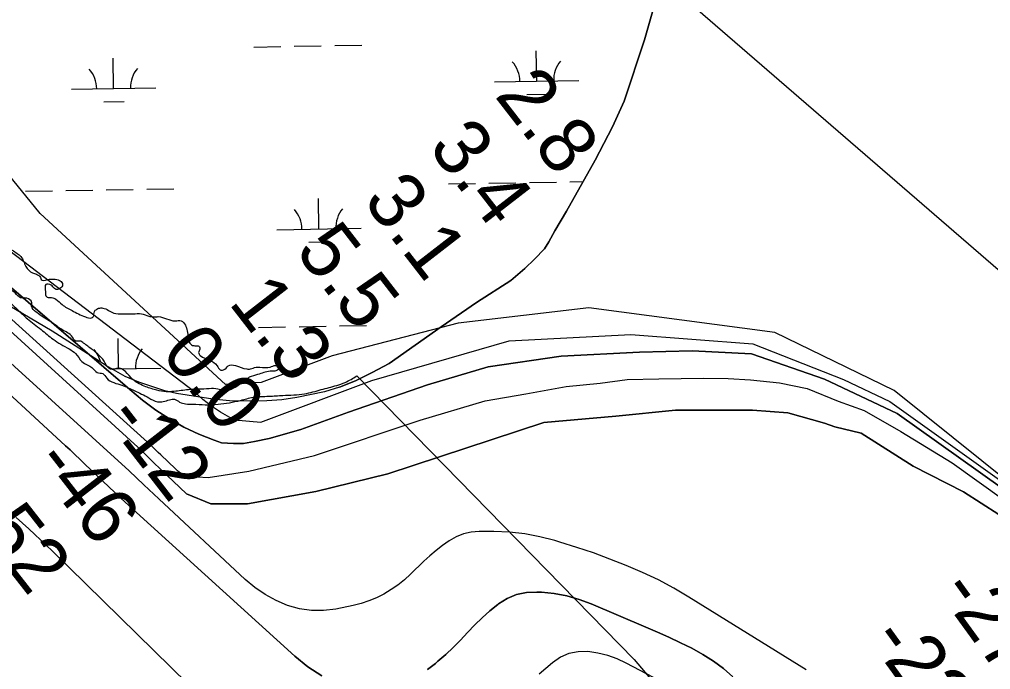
# Model space of a CAD drawing. Extents: x 3892998 to 3931244, y 278583 to 304547.
# Drawn here: x 3911880 to 3913032, y 292369 to 293140 of the extents above; entities that cross this region are included whole.
import ezdxf

# ---------------------------------------------------------------- set-up
doc = ezdxf.new("R2010")
doc.units = 0
for name, color, linetype in [('V-GRID-MAJR', 7, 'Continuous'), ('V-RIVR-EDGE', 7, 'Continuous'), ('V-RIVR-RANG', 7, 'Continuous'), ('V-TOPO-DPTH', 7, 'Continuous'), ('V-TOPO-MAJR', 7, 'Continuous'), ('V-TOPO-MINR', 7, 'Continuous'), ('V-TOPO-SHOR', 7, 'Continuous'), ('V-TOPO-WATR', 7, 'Continuous'), ('V-UTIL-LINE', 7, 'Continuous'), ('V-WETL-SWMP', 7, 'Continuous')]:
    doc.layers.add(name, color=color, linetype=linetype)

msp = doc.modelspace()

# ---------------------------------------------------------------- linework, layer by layer
at = {"layer": 'V-GRID-MAJR'}
msp.add_spline([(3913205.7, 284291.2), (3913100.9, 290347.6), (3912996, 296407.6), (3912891.1, 302467.5), (3912891, 302471)], degree=3, dxfattribs=at)
at = {"layer": 'V-RIVR-EDGE'}
for p, q in [((3912279.7, 292717.3), (3912608.9, 292380.9)), ((3912608.9, 292380.9), (3912865, 292078.8))]:
    msp.add_line(p, q, dxfattribs=at)
msp.add_spline([(3911791.9, 293031.1), (3911788.2, 293020.2), (3911781.2, 293014.2), (3911750.3, 292994.6), (3911722.9, 292976.8), (3911718.6, 292974.1), (3911715.9, 292969.8), (3911715.6, 292965.1), (3911717.6, 292958.5), (3911723.9, 292953.5), (3911730.9, 292952.8), (3911742.5, 292955.1), (3911750.8, 292957.7), (3911758.1, 292958), (3911775.4, 292952), (3911792, 292943.3), (3911808, 292932), (3911822.9, 292920), (3911838.5, 292902), (3911846.8, 292890), (3911854.7, 292878), (3911865.3, 292870.3), (3911877, 292862.6), (3911881.3, 292859), (3911887.2, 292847.3), (3911895.2, 292839.7), (3911899.8, 292838), (3911904.5, 292834), (3911905.5, 292831.7), (3911912.8, 292831.6), (3911927.1, 292830.6), (3911929.1, 292829.3), (3911930.7, 292824.3), (3911928.7, 292822), (3911923.4, 292820), (3911919.4, 292823), (3911917.1, 292825), (3911911.1, 292826), (3911910.4, 292817.3), (3911910.4, 292815), (3911912.7, 292810.7), (3911917.7, 292810.3), (3911923, 292808.3), (3911930.3, 292802), (3911942, 292795), (3911957.9, 292787.3), (3911965.2, 292786.3), (3911967.2, 292787.6), (3911968.6, 292793.9), (3911969.6, 292795.2), (3911973.6, 292797.6), (3911978.6, 292797.9), (3911991.5, 292791.9), (3912002.5, 292791.2), (3912014.4, 292791.1), (3912024.4, 292791.1), (3912033.1, 292788.4), (3912038.4, 292787.4), (3912044.4, 292787.7), (3912064.3, 292782.7), (3912071.6, 292782.7), (3912074.3, 292780.7), (3912079.2, 292767), (3912080.5, 292759.1), (3912083.9, 292754.1), (3912089.2, 292753.1), (3912093.2, 292752), (3912093.5, 292749.1), (3912092.1, 292745.1), (3912094.1, 292741.7), (3912105.1, 292736.1), (3912114.1, 292729.4), (3912117.7, 292724.7), (3912121.7, 292724.4), (3912127.4, 292729.3), (3912136, 292729.7), (3912149.3, 292725.6), (3912153.6, 292725.6), (3912160.3, 292727.6), (3912164.9, 292727.6), (3912176.9, 292727.9), (3912183.9, 292729.9), (3912189.2, 292727.9), (3912187.5, 292725.2), (3912176.9, 292722.9), (3912162.2, 292719), (3912152.3, 292715.7), (3912141.6, 292707.7), (3912130.6, 292701.4), (3912121.6, 292699.8), (3912115, 292701.8), (3912104.7, 292702.1), (3912080.1, 292700.9), (3912062.8, 292698.9), (3912053.8, 292698.6), (3912042.8, 292700.3), (3912029.5, 292704.6), (3912014.3, 292713), (3911995.7, 292726.3), (3911991.7, 292725), (3911984, 292728), (3911981.4, 292732.4), (3911974.8, 292741.4), (3911965.8, 292748.7), (3911955.8, 292756.4), (3911951.2, 292758.7), (3911946.5, 292758.7), (3911942.6, 292763.4), (3911929.9, 292772.4), (3911919.6, 292779.7), (3911909, 292786.4), (3911899.4, 292793.1), (3911894.1, 292800.1), (3911894.4, 292804.1), (3911893.4, 292806.4), (3911886.5, 292809.8), (3911881.1, 292810.1), (3911874.5, 292815.8), (3911864.6, 292822.1), (3911848, 292836.8), (3911832, 292848.1), (3911815.8, 292856.1), (3911809.4, 292857.5), (3911808.8, 292854.8), (3911810.4, 292849.5), (3911813.1, 292846.5), (3911818.4, 292845.8), (3911826.7, 292845.8), (3911827.7, 292842.8), (3911832, 292831.5), (3911837.3, 292826.8), (3911850.9, 292816.8), (3911867.5, 292804.8), (3911877.5, 292796.1), (3911889.1, 292785.1), (3911905.3, 292772.5), (3911919.6, 292760.8), (3911938.5, 292749.4), (3911946.2, 292743.8), (3911953.8, 292734.4), (3911960.1, 292730.4), (3911965.7, 292727.4), (3911972, 292721.4), (3911978.4, 292720.1), (3911983.3, 292714.7), (3912001.3, 292706.4), (3912015.9, 292700), (3912033.2, 292691.3), (3912043.5, 292686.7), (3912050.1, 292687), (3912057.8, 292689), (3912063.4, 292689.6), (3912069.7, 292686.3), (3912076.7, 292684.2), (3912085.3, 292683.9), (3912100, 292683.2), (3912115.3, 292683.8), (3912141.9, 292688.4), (3912156.9, 292692), (3912175.5, 292693.3), (3912192.1, 292694.3), (3912217.7, 292696.2), (3912237.7, 292701.1), (3912256, 292706.1), (3912266, 292709.7), (3912279.7, 292717.3)], degree=3, dxfattribs=at)
at = {"layer": 'V-TOPO-DPTH'}
for points in [[(3910798.2, 294022.9), (3910835.5, 293972.8), (3910873.9, 293923.5), (3910913, 293874.7), (3910944, 293836.7), (3910968.2, 293807.5), (3910992.7, 293778.4), (3911499.9, 293140), (3912010.4, 292701.1), (3912025.6, 292688.7), (3912041.3, 292676.9), (3912057.8, 292666.3), (3912074.8, 292656.6), (3912092.4, 292648.3), (3912110.6, 292641), (3912119.3, 292637.8)], [(3912077.7, 292577.3), (3912046.4, 292607.2), (3912039, 292614.4), (3912031.6, 292621.6), (3912024.3, 292628.9), (3911502.2, 293104.5), (3911491.4, 293117.8), (3911480.7, 293131.2), (3911470.1, 293144.7), (3911030.1, 293655.2), (3911016.3, 293672.1), (3911002.9, 293689.4), (3910967.6, 293736.7), (3910961.5, 293744.9), (3910955.5, 293753.1), (3910949.6, 293761.4), (3910943.7, 293769.7), (3910895.3, 293839.1), (3910865.2, 293882.1), (3910835.2, 293925.2), (3910805.2, 293968.3)], [(3910805.2, 293968.3), (3910835.2, 293925.2), (3910865.2, 293882.1), (3910895.3, 293839.1), (3910943.7, 293769.7), (3910949.6, 293761.4), (3910955.5, 293753.1), (3910961.5, 293744.9), (3910967.6, 293736.7), (3911002.9, 293689.4), (3911016.3, 293672.1), (3911030.1, 293655.2), (3911470.1, 293144.7), (3911480.7, 293131.2), (3911491.4, 293117.8), (3911502.2, 293104.5), (3912024.3, 292628.9), (3912031.6, 292621.6), (3912039, 292614.4), (3912046.4, 292607.2), (3912077.7, 292577.3)], [(3911468.2, 293065.1), (3911934.3, 292634.6), (3911939.9, 292629.6), (3911957.1, 292612.8), (3911971.3, 292599.2), (3911985.5, 292585.7), (3911999.8, 292572.4), (3912014.3, 292559.1), (3912206.3, 292384.7), (3912221.9, 292372.4), (3912238.4, 292361.7)], [(3911468.2, 293065.1), (3911934.3, 292634.6), (3911939.9, 292629.6), (3911957.1, 292612.8), (3911971.3, 292599.2), (3911985.5, 292585.7), (3911999.8, 292572.4), (3912014.3, 292559.1), (3912206.3, 292384.7), (3912221.9, 292372.4), (3912238.4, 292361.7)], [(3912812.9, 292368.8), (3912673.8, 292454.9), (3912655.8, 292465.5), (3912637.5, 292475.4), (3912618.6, 292484.3), (3912599.5, 292492.6), (3912580, 292500.1), (3912560.4, 292507.3), (3912540.6, 292514), (3912520.7, 292520.2), (3912514.8, 292522), (3912497, 292526.5), (3912479, 292529.9), (3912460.8, 292531.8), (3912442.4, 292532.6), (3912424.9, 292532.7), (3912415.4, 292531.8), (3912406.3, 292529.9), (3912397.7, 292526.4), (3912389.4, 292521.8), (3912381.5, 292516.1), (3912373.9, 292510.2), (3912366.5, 292503.9), (3912359.4, 292497.4), (3912343.6, 292482.1), (3912336.3, 292475.5), (3912328.6, 292469.3), (3912320.5, 292463.8), (3912312, 292458.6), (3912303.2, 292454.2), (3912294.2, 292450.4), (3912284.8, 292447.4), (3912275.3, 292445), (3912255.1, 292440.8), (3912240.5, 292439), (3912226, 292438.9), (3912211.7, 292441.2), (3912197.6, 292445.1), (3912184, 292451.1), (3912171, 292458), (3912158.9, 292466.5), (3912147.5, 292476), (3912045, 292571.4), (3912027.3, 292588), (3912009.8, 292604.7), (3911509.4, 293060)], [(3912812.9, 292368.8), (3912673.8, 292454.9), (3912655.8, 292465.5), (3912637.5, 292475.4), (3912618.6, 292484.3), (3912599.5, 292492.6), (3912580, 292500.1), (3912560.4, 292507.3), (3912540.6, 292514), (3912520.7, 292520.2), (3912514.8, 292522), (3912497, 292526.5), (3912479, 292529.9), (3912460.8, 292531.8), (3912442.4, 292532.6), (3912424.9, 292532.7), (3912415.4, 292531.8), (3912406.3, 292529.9), (3912397.7, 292526.4), (3912389.4, 292521.8), (3912381.5, 292516.1), (3912373.9, 292510.2), (3912366.5, 292503.9), (3912359.4, 292497.4), (3912343.6, 292482.1), (3912336.3, 292475.5), (3912328.6, 292469.3), (3912320.5, 292463.8), (3912312, 292458.6), (3912303.2, 292454.2), (3912294.2, 292450.4), (3912284.8, 292447.4), (3912275.3, 292445), (3912255.1, 292440.8), (3912240.5, 292439), (3912226, 292438.9), (3912211.7, 292441.2), (3912197.6, 292445.1), (3912184, 292451.1), (3912171, 292458), (3912158.9, 292466.5), (3912147.5, 292476), (3912045, 292571.4), (3912027.3, 292588), (3912009.8, 292604.7), (3911509.4, 293060)], [(3912119.3, 292637.8), (3912133.6, 292637.1), (3912145.6, 292637), (3912158.5, 292639.6), (3912175.7, 292643), (3912213.4, 292654), (3912270.1, 292674.5), (3912363.6, 292706.8), (3912435.7, 292728.1), (3912522.3, 292740.8), (3912615, 292745.7), (3912677.6, 292747.2), (3912747.9, 292743.6), (3912834.4, 292713.4), (3912920.9, 292672.9), (3913069, 292567)], [(3913080.7, 292523.4), (3913041.5, 292552.9), (3912999.6, 292580), (3912939.6, 292610.2), (3912878.2, 292649.4), (3912846.7, 292657), (3912834.7, 292661.5), (3912791.2, 292673.6), (3912749.2, 292676.7), (3912707.2, 292676.8), (3912657.7, 292676.9), (3912587.1, 292669.6), (3912501.6, 292662.3), (3912316.8, 292601.2), (3912231.3, 292580.4), (3912150.2, 292565.6), (3912106.7, 292565.7), (3912077.7, 292577.3)], [(3912077.7, 292577.3), (3912106.7, 292565.7), (3912150.2, 292565.6), (3912231.3, 292580.4), (3912316.8, 292601.2), (3912501.6, 292662.3), (3912587.1, 292669.6), (3912657.7, 292676.9), (3912707.2, 292676.8), (3912749.2, 292676.7), (3912791.2, 292673.6), (3912834.7, 292661.5), (3912846.7, 292657), (3912878.2, 292649.4), (3912939.6, 292610.2), (3912999.6, 292580), (3913041.5, 292552.9), (3913080.7, 292523.4)], [(3912363.7, 292368.9), (3912373, 292376.3), (3912376.1, 292378.9), (3912385.4, 292387), (3912394.3, 292395.3), (3912402.9, 292404), (3912411.3, 292413), (3912419.7, 292421.9), (3912428.4, 292430.5), (3912437.5, 292438.6), (3912447, 292446.3), (3912447.8, 292446.9), (3912458.3, 292453.3), (3912469.4, 292458.1), (3912481.2, 292460.4), (3912493.5, 292461), (3912498.8, 292460.7), (3912514, 292459.1), (3912529, 292456.4), (3912543.6, 292452.2), (3912557.9, 292447), (3912622.6, 292419.4), (3912636.4, 292413.4), (3912650, 292407.3), (3912663.6, 292400.8), (3912677.1, 292394.2), (3912690.1, 292387), (3912702.7, 292379), (3912714.6, 292370.1), (3912726, 292360.5)], [(3912363.7, 292368.9), (3912373, 292376.3), (3912376.1, 292378.9), (3912385.4, 292387), (3912394.3, 292395.3), (3912402.9, 292404), (3912411.3, 292413), (3912419.7, 292421.9), (3912428.4, 292430.5), (3912437.5, 292438.6), (3912447, 292446.3), (3912447.8, 292446.9), (3912458.3, 292453.3), (3912469.4, 292458.1), (3912481.2, 292460.4), (3912493.5, 292461), (3912498.8, 292460.7), (3912514, 292459.1), (3912529, 292456.4), (3912543.6, 292452.2), (3912557.9, 292447), (3912622.6, 292419.4), (3912636.4, 292413.4), (3912650, 292407.3), (3912663.6, 292400.8), (3912677.1, 292394.2), (3912690.1, 292387), (3912702.7, 292379), (3912714.6, 292370.1), (3912726, 292360.5)]]:
    msp.add_lwpolyline(points, dxfattribs=at)
at = {"layer": 'V-TOPO-MAJR'}
for points in [[(3912180.2, 292253), (3911918.6, 292509.7), (3911911.7, 292516.3), (3911904.8, 292522.8), (3911897.9, 292529.3), (3911890.9, 292535.8), (3911875.9, 292549.3)], [(3912736.5, 292304.5), (3912599.4, 292376.7), (3912588.5, 292381.7), (3912577.4, 292385.8), (3912565.8, 292388.5), (3912554, 292390.4), (3912542.5, 292390.2), (3912531.5, 292388.1), (3912521.4, 292383.5), (3912511.8, 292377.1), (3912496, 292363.4)]]:
    msp.add_lwpolyline(points, dxfattribs=at)
at = {"layer": 'V-TOPO-MINR'}
for points in [[(3912134.6, 292665.3), (3912129.4, 292667.9), (3912118.1, 292674.2), (3912107.3, 292681.3), (3912097.2, 292689.3), (3912087.6, 292698), (3911515.7, 293134.1), (3911513, 293137.8), (3910985.3, 293857.1), (3910673.3, 294230.6)], [(3912119.3, 292637.8), (3912110.6, 292641), (3912092.4, 292648.3), (3912074.8, 292656.6), (3912057.8, 292666.3), (3912041.3, 292676.9), (3912025.6, 292688.7), (3912010.4, 292701.1), (3911499.9, 293140), (3910992.7, 293778.4), (3910968.2, 293807.5), (3910944, 293836.7), (3910913, 293874.7), (3910873.9, 293923.5), (3910835.5, 293972.8), (3910798.2, 294022.9)], [(3912077.7, 292577.3), (3912046.4, 292607.2), (3912039, 292614.4), (3912031.6, 292621.6), (3912024.3, 292628.9), (3911502.2, 293104.5), (3911491.4, 293117.8), (3911480.7, 293131.2), (3911470.1, 293144.7), (3911030.1, 293655.2), (3911016.3, 293672.1), (3911002.9, 293689.4), (3910967.6, 293736.7), (3910961.5, 293744.9), (3910955.5, 293753.1), (3910949.6, 293761.4), (3910943.7, 293769.7), (3910895.3, 293839.1), (3910865.2, 293882.1), (3910835.2, 293925.2), (3910805.2, 293968.3)], [(3912077.6, 292598.4), (3912075.4, 292599.4), (3912072.5, 292601), (3912069.7, 292602.8), (3912067.1, 292604.8), (3912064.6, 292607), (3912047.2, 292623.8), (3912044.4, 292626.6), (3912041.6, 292629.4), (3912038.8, 292632.2), (3912036, 292635), (3911515, 293105.4), (3911507.5, 293114.5), (3911500.1, 293123.7), (3911492.9, 293132.9), (3911485.7, 293142.3)], [(3912238.4, 292361.7), (3912221.9, 292372.4), (3912206.3, 292384.7), (3912014.3, 292559.1), (3911999.8, 292572.4), (3911985.5, 292585.7), (3911971.3, 292599.2), (3911957.1, 292612.8), (3911939.9, 292629.6), (3911934.3, 292634.6), (3911468.2, 293065.1)], [(3912812.9, 292368.8), (3912673.8, 292454.9), (3912655.8, 292465.5), (3912637.5, 292475.4), (3912618.6, 292484.3), (3912599.5, 292492.6), (3912580, 292500.1), (3912560.4, 292507.3), (3912540.6, 292514), (3912520.7, 292520.2), (3912514.8, 292522), (3912497, 292526.5), (3912479, 292529.9), (3912460.8, 292531.8), (3912442.4, 292532.6), (3912424.9, 292532.7), (3912415.4, 292531.8), (3912406.3, 292529.9), (3912397.7, 292526.4), (3912389.4, 292521.8), (3912381.5, 292516.1), (3912373.9, 292510.2), (3912366.5, 292503.9), (3912359.4, 292497.4), (3912343.6, 292482.1), (3912336.3, 292475.5), (3912328.6, 292469.3), (3912320.5, 292463.8), (3912312, 292458.6), (3912303.2, 292454.2), (3912294.2, 292450.4), (3912284.8, 292447.4), (3912275.3, 292445), (3912255.1, 292440.8), (3912240.5, 292439), (3912226, 292438.9), (3912211.7, 292441.2), (3912197.6, 292445.1), (3912184, 292451.1), (3912171, 292458), (3912158.9, 292466.5), (3912147.5, 292476), (3912045, 292571.4), (3912027.3, 292588), (3912009.8, 292604.7), (3911509.4, 293060)], [(3912134.6, 292665.3), (3912166.1, 292662.4), (3912297.6, 292712), (3912460.5, 292758.9), (3912604.9, 292766.5), (3912749.4, 292755.6), (3912856.9, 292713.3), (3912912, 292686.9), (3913042.1, 292594.1), (3913128.2, 292525.7), (3913143.4, 292511.4), (3913155.1, 292493.8), (3913163.8, 292474.1), (3913179.9, 292409.4), (3913207.4, 292260.8), (3913251.4, 292019.8), (3913282.5, 291857.5), (3913277.9, 291800.5), (3913271.7, 291735.9), (3913261, 291666.9), (3913236.9, 291626.4)], [(3913069, 292567), (3912920.9, 292672.9), (3912834.4, 292713.4), (3912747.9, 292743.6), (3912677.6, 292747.2), (3912615, 292745.7), (3912522.3, 292740.8), (3912435.7, 292728.1), (3912363.6, 292706.8), (3912270.1, 292674.5), (3912213.4, 292654), (3912175.7, 292643), (3912158.5, 292639.6), (3912145.6, 292637), (3912133.6, 292637.1), (3912119.3, 292637.8)], [(3912077.6, 292598.4), (3912103.5, 292596.8), (3912151.6, 292604.4), (3912229.6, 292623.1), (3912354.9, 292664.8), (3912432.2, 292687.8), (3912480.2, 292696.3), (3912528.3, 292704.7), (3912568.6, 292708.9), (3912600.3, 292713.1), (3912638, 292713.9), (3912691.2, 292714.6), (3912720.4, 292714.5), (3912746.9, 292712.8), (3912781.2, 292709.2), (3912813.8, 292702.3), (3912850.6, 292687.6), (3912881.5, 292676.4), (3912925.2, 292651.4), (3912986, 292614.4), (3913108.4, 292526.5)], [(3912077.7, 292577.3), (3912106.7, 292565.7), (3912150.2, 292565.6), (3912231.3, 292580.4), (3912316.8, 292601.2), (3912501.6, 292662.3), (3912587.1, 292669.6), (3912657.7, 292676.9), (3912707.2, 292676.8), (3912749.2, 292676.7), (3912791.2, 292673.6), (3912834.7, 292661.5), (3912846.7, 292657), (3912878.2, 292649.4), (3912939.6, 292610.2), (3912999.6, 292580), (3913041.5, 292552.9), (3913080.7, 292523.4)], [(3912726, 292360.5), (3912714.6, 292370.1), (3912702.7, 292379), (3912690.1, 292387), (3912677.1, 292394.2), (3912663.6, 292400.8), (3912650, 292407.3), (3912636.4, 292413.4), (3912622.6, 292419.4), (3912557.9, 292447), (3912543.6, 292452.2), (3912529, 292456.4), (3912514, 292459.1), (3912498.8, 292460.7), (3912493.5, 292461), (3912481.2, 292460.4), (3912469.4, 292458.1), (3912458.3, 292453.3), (3912447.8, 292446.9), (3912447, 292446.3), (3912437.5, 292438.6), (3912428.4, 292430.5), (3912419.7, 292421.9), (3912411.3, 292413), (3912402.9, 292404), (3912394.3, 292395.3), (3912385.4, 292387), (3912376.1, 292378.9), (3912373, 292376.3), (3912363.7, 292368.9)]]:
    msp.add_lwpolyline(points, dxfattribs=at)
at = {"layer": 'V-TOPO-SHOR'}
msp.add_lwpolyline([(3912259.4, 292703.9), (3912278.1, 292711.6), (3912297.9, 292721.6), (3912318, 292732.3), (3912379.8, 292775.8), (3912421.6, 292804.6), (3912462.7, 292830.5), (3912479, 292844.9), (3912490.4, 292855.9), (3912502.6, 292868), (3912507.7, 292876.3), (3912514.7, 292889.7), (3912528.6, 292913), (3912562.7, 292973.2), (3912583, 293012.8), (3912597, 293043.4), (3912621.1, 293116.2), (3912630.5, 293149.5)], dxfattribs=at)
at = {"layer": 'V-TOPO-WATR'}
msp.add_lwpolyline([(3913308.6, 291650.1), (3913318, 291732.7), (3913318.4, 291754.2), (3913318.2, 291769.7), (3913317.2, 291785.1), (3913315.2, 291800.5), (3913312.4, 291815.7), (3913174.6, 292454.8), (3913167.1, 292477.4), (3913156.8, 292498.3), (3913142.2, 292516.5), (3913125, 292533), (3912917.3, 292700), (3912775.7, 292768.7), (3912555.1, 292798.1), (3912400.1, 292780.1), (3912250.4, 292741.1), (3912166.2, 292709.7), (3912124.2, 292707.2), (3911904.1, 292910.1), (3911649.2, 293223.9)], dxfattribs=at)
at = {"layer": 'V-UTIL-LINE'}
msp.add_line((3913277.9, 292637.7), (3912593.9, 293229.9), dxfattribs=at)
at = {"layer": 'V-WETL-SWMP'}
for p, q in [((3912157.7, 293107.6), (3912189.6, 293108.2)), ((3912205.6, 293108.5), (3912237.6, 293109)), ((3912253.6, 293109.3), (3912285.6, 293109.8)), ((3912493.2, 293067), (3912492.6, 293103)), ((3911991.4, 293058.3), (3911990.8, 293094.3)), ((3912443.3, 293066.1), (3912543.2, 293067.9)), ((3911941.4, 293057.4), (3912041.4, 293059.2)), ((3912481.5, 293051.4), (3912505.5, 293051.8)), ((3911979.7, 293042.7), (3912003.7, 293043.1)), ((3912388.5, 292945.1), (3912420.5, 292945.6)), ((3912436.5, 292945.9), (3912468.5, 292946.5)), ((3912484.5, 292946.8), (3912516.5, 292947.3)), ((3912532.5, 292947.6), (3912548.4, 292947.9)), ((3911886.7, 292936.4), (3911918.7, 292937)), ((3911934.7, 292937.2), (3911966.7, 292937.8)), ((3911982.7, 292938.1), (3912014.6, 292938.6)), ((3912030.6, 292938.9), (3912062.6, 292939.5)), ((3912234.8, 292891.7), (3912234.2, 292927.7)), ((3912184.8, 292890.8), (3912284.8, 292892.5)), ((3912223.1, 292876), (3912247.1, 292876.5)), ((3912163.4, 292775), (3912195.4, 292775.6)), ((3912211.4, 292775.8), (3912243.4, 292776.4)), ((3912259.4, 292776.7), (3912291.4, 292777.2)), ((3911997.2, 292725.7), (3911996.6, 292761.7)), ((3911989.7, 292725.6), (3912047.2, 292726.5))]:
    msp.add_line(p, q, dxfattribs=at)
msp.add_lwpolyline([(3912630.5, 293149.5), (3912621.1, 293116.2), (3912597, 293043.4), (3912583, 293012.8), (3912562.7, 292973.2), (3912528.6, 292913), (3912514.7, 292889.7), (3912507.7, 292876.3), (3912502.6, 292868), (3912490.4, 292855.9), (3912479, 292844.9), (3912462.7, 292830.5), (3912421.6, 292804.6), (3912379.8, 292775.8), (3912318, 292732.3), (3912297.9, 292721.6), (3912278.1, 292711.6), (3912259.4, 292703.9), (3912241.3, 292698.3), (3912208.8, 292691.8), (3912191, 292689), (3912172.9, 292687.8), (3912152.6, 292687.5), (3912128.9, 292687.8), (3912109.1, 292689.6), (3912066.1, 292696.4), (3912052.2, 292699.5), (3912035.5, 292705.2), (3912021.1, 292710.1), (3912005.2, 292716.7), (3911982.9, 292729.5), (3911918.3, 292770.6), (3911850.3, 292810.5)], dxfattribs=at)
for centre, start, end in [((3912548.5, 293068.4), 140.2199, 181.7635), ((3911936.2, 293057.8), 0.2199, 41.7635), ((3912046.6, 293059.7), 140.2199, 181.7635), ((3912438, 293066.5), 0.2199, 41.7635), ((3912179.6, 292891.2), 0.2199, 41.7635), ((3912290, 292893.1), 140.2199, 181.7635), ((3911941.9, 292725.2), 14.1094, 41.7635), ((3912052.4, 292727.1), 140.2199, 181.7635)]:
    msp.add_arc(centre, 35.2, start, end, dxfattribs=at)

# ---------------------------------------------------------------- texts
at = {"layer": 'V-RIVR-RANG'}
for s, rotation, p in [('2.8', 307.7683, (3912442.3, 293049.8)), ('3.4', 307.7683, (3912363.4, 292988.4)), ('3.1', 307.7683, (3912286, 292925.1)), ('5.5', 307.7683, (3912205.6, 292865.5)), ('1.3', 307.7683, (3912126.7, 292804.1)), ('0.0', 307.7683, (3912046.1, 292744.9)), ('-12', 307.7683, (3911980.1, 292666.8)), ('-46', 307.7683, (3911894.4, 292614.1)), ('-52', 308.0484, (3911812.4, 292556.1)), ('-27', 305.9583, (3912968.5, 292461.3)), ('-22', 305.9583, (3912886.2, 292404.5))]:
    msp.add_text(s, height=67, rotation=rotation, dxfattribs=at).set_placement(p)

doc.saveas('drawing.dxf')
